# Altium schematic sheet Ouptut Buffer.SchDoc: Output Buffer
size 431 x 279 mm; Date: Not shown in title block; ApprovedBy: Not shown in title block; CheckedBy: Not shown in title block; Author: Not shown in title block; CompanyName: Not shown in title block; Engineer: Not shown in title block; Organization: Not shown in title block; Address1: Not shown in title block; Address2: Not shown in title block; Address3: Not shown in title block; Address4: Not shown in title block; DocumentNumber: 1; Revision: Use project parameter SCH_Rev; SheetNumber: 13; SheetTotal: 15; PageSetup: Record=PageOptions¦CenterHorizontal=True¦CenterVertical=True¦PrintScale=1.00¦XCorrection=1.00¦YCorrection=1.00¦PrintKind=0¦BorderSize=5000000¦LeftOffset=0¦BottomOffset=0¦Orientation=2¦PaperLength=1000¦PaperWidth=1000¦Scale=100¦PaperSource=15¦PrintQuality=600¦MediaType=1¦DitherType=10¦PaperKind=Letter¦PrintScaleMode=1
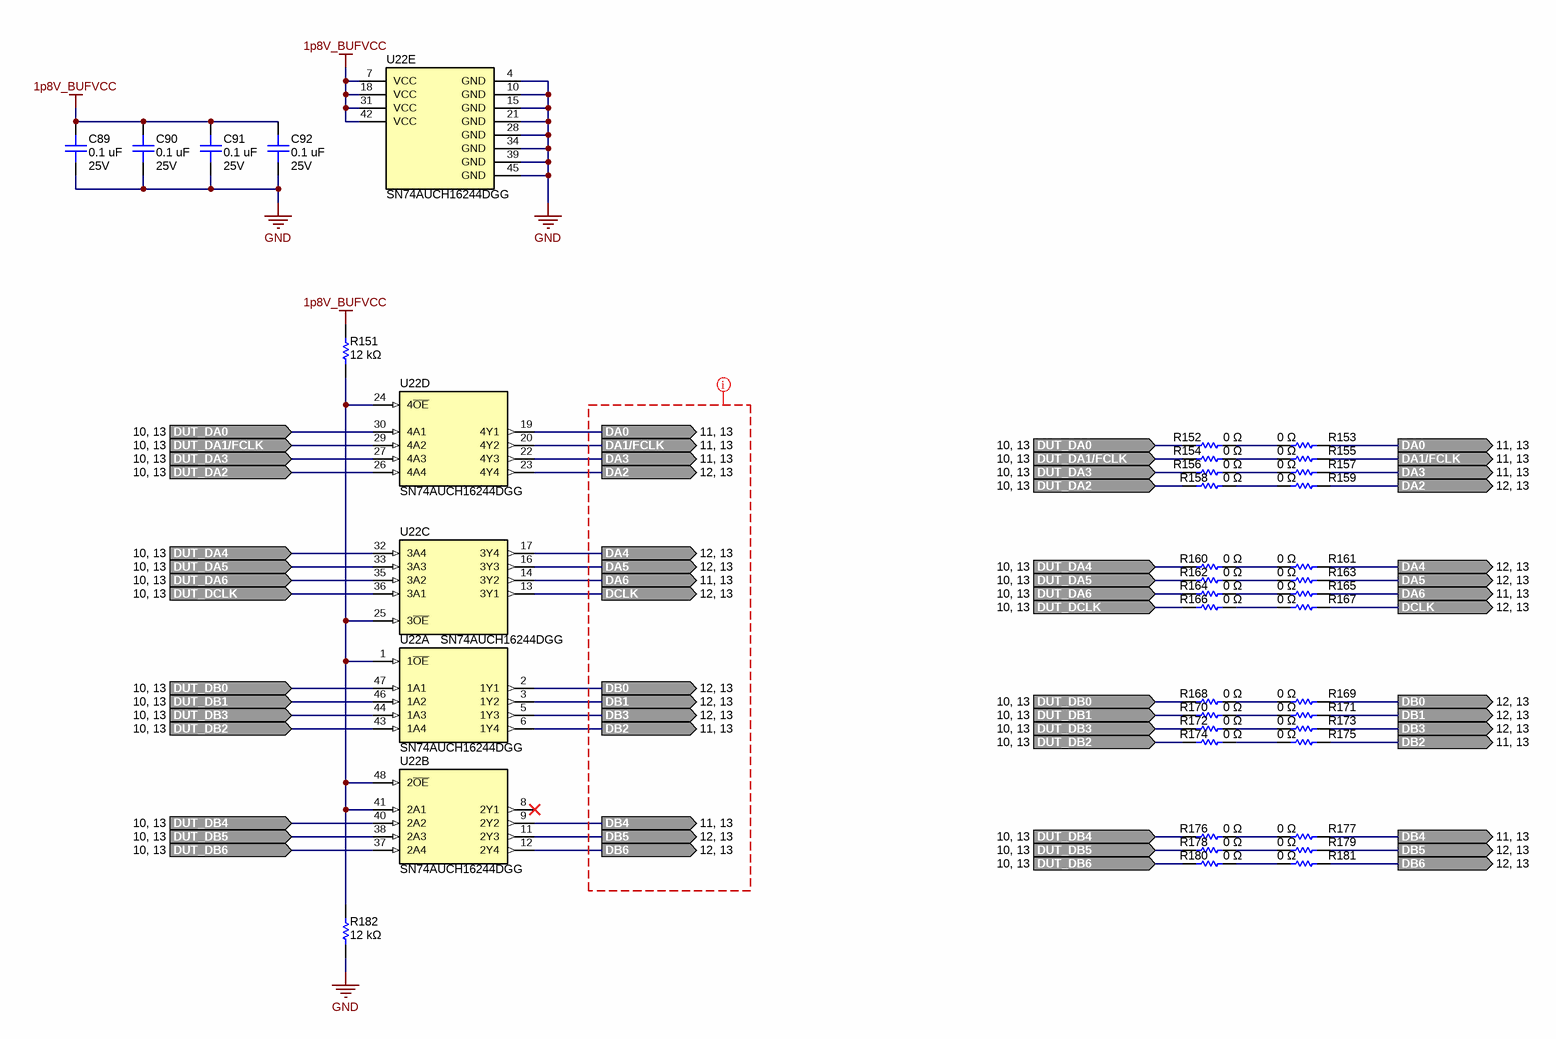
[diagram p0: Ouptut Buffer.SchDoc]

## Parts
C89  value 0.1 uF  Voltage - Rated: 25V  [0402L_cap]  (hidden comment: GRT155R71E104KE01J)
C90  value 0.1 uF  Voltage - Rated: 25V  [0402L_cap]  (hidden comment: GRT155R71E104KE01J)
C91  value 0.1 uF  Voltage - Rated: 25V  [0402L_cap]  (hidden comment: GRT155R71E104KE01J)
C92  value 0.1 uF  Voltage - Rated: 25V  [0402L_cap]  (hidden comment: GRT155R71E104KE01J)
R151  value 12 kΩ  [0201]  (hidden comment: ERJ-1GNJ123C)
R152  value 0 Ω  [0201]  (hidden comment: ERJ-1GN0R00C)
R153  value 0 Ω  [0201]  (hidden comment: ERJ-1GN0R00C)
R154  value 0 Ω  [0201]  (hidden comment: ERJ-1GN0R00C)
R155  value 0 Ω  [0201]  (hidden comment: ERJ-1GN0R00C)
R156  value 0 Ω  [0201]  (hidden comment: ERJ-1GN0R00C)
R157  value 0 Ω  [0201]  (hidden comment: ERJ-1GN0R00C)
R158  value 0 Ω  [0201]  (hidden comment: ERJ-1GN0R00C)
R159  value 0 Ω  [0201]  (hidden comment: ERJ-1GN0R00C)
R160  value 0 Ω  [0201]  (hidden comment: ERJ-1GN0R00C)
R161  value 0 Ω  [0201]  (hidden comment: ERJ-1GN0R00C)
R162  value 0 Ω  [0201]  (hidden comment: ERJ-1GN0R00C)
R163  value 0 Ω  [0201]  (hidden comment: ERJ-1GN0R00C)
R164  value 0 Ω  [0201]  (hidden comment: ERJ-1GN0R00C)
R165  value 0 Ω  [0201]  (hidden comment: ERJ-1GN0R00C)
R166  value 0 Ω  [0201]  (hidden comment: ERJ-1GN0R00C)
R167  value 0 Ω  [0201]  (hidden comment: ERJ-1GN0R00C)
R168  value 0 Ω  [0201]  (hidden comment: ERJ-1GN0R00C)
R169  value 0 Ω  [0201]  (hidden comment: ERJ-1GN0R00C)
R170  value 0 Ω  [0201]  (hidden comment: ERJ-1GN0R00C)
R171  value 0 Ω  [0201]  (hidden comment: ERJ-1GN0R00C)
R172  value 0 Ω  [0201]  (hidden comment: ERJ-1GN0R00C)
R173  value 0 Ω  [0201]  (hidden comment: ERJ-1GN0R00C)
R174  value 0 Ω  [0201]  (hidden comment: ERJ-1GN0R00C)
R175  value 0 Ω  [0201]  (hidden comment: ERJ-1GN0R00C)
R176  value 0 Ω  [0201]  (hidden comment: ERJ-1GN0R00C)
R177  value 0 Ω  [0201]  (hidden comment: ERJ-1GN0R00C)
R178  value 0 Ω  [0201]  (hidden comment: ERJ-1GN0R00C)
R179  value 0 Ω  [0201]  (hidden comment: ERJ-1GN0R00C)
R180  value 0 Ω  [0201]  (hidden comment: ERJ-1GN0R00C)
R181  value 0 Ω  [0201]  (hidden comment: ERJ-1GN0R00C)
R182  value 12 kΩ  [0201]  (hidden comment: ERJ-1GNJ123C)
U22  SN74AUCH16244DGG  [DGG0048A]  (parts A,B,C,D,E of 5)

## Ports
DA0 (out, see 11, 13), DA1/FCLK (out, see 11, 13), DA2 (out, see 12, 13), DA3 (out, see 11, 13), DA4 (out, see 12, 13), DA5 (out, see 12, 13), DA6 (out, see 11, 13), DB0 (out, see 12, 13), DB1 (out, see 12, 13), DB2 (out, see 11, 13), DB3 (out, see 12, 13), DB4 (out, see 11, 13), DB5 (out, see 12, 13), DB6 (out, see 12, 13), DCLK (out, see 12, 13), DUT_DA0 (in, see 10, 13), DUT_DA1/FCLK (in, see 10, 13), DUT_DA2 (in, see 10, 13), DUT_DA3 (in, see 10, 13), DUT_DA4 (in, see 10, 13), DUT_DA5 (in, see 10, 13), DUT_DA6 (in, see 10, 13), DUT_DB0 (in, see 10, 13), DUT_DB1 (in, see 10, 13), DUT_DB2 (in, see 10, 13), DUT_DB3 (in, see 10, 13), DUT_DB4 (in, see 10, 13), DUT_DB5 (in, see 10, 13), DUT_DB6 (in, see 10, 13), DUT_DCLK (in, see 10, 13)

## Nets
1p8V_BUFVCC: C89.2 C90.2 C91.2 C92.2 R151.2 U22.7(VCC) U22.18(VCC) U22.31(VCC) U22.42(VCC)
GND: C89.1 C90.1 C91.1 C92.1 R182.1 U22.4(GND) U22.10(GND) U22.15(GND) U22.21(GND) U22.28(GND) U22.34(GND) U22.39(GND) U22.45(GND)
DA0: R153.2 U22.19(4Y1) ; port DA0
DA1/FCLK: R155.2 U22.20(4Y2) ; port DA1/FCLK
DA2: R159.2 U22.23(4Y4) ; port DA2
DA3: R157.2 U22.22(4Y3) ; port DA3
DA4: R161.2 U22.17(3Y4) ; port DA4
DA5: R163.2 U22.16(3Y3) ; port DA5
DA6: R165.2 U22.14(3Y2) ; port DA6
DB0: R169.2 U22.2(1Y1) ; port DB0
DB1: R171.2 U22.3(1Y2) ; port DB1
DB2: R175.2 U22.6(1Y4) ; port DB2
DB3: R173.2 U22.5(1Y3) ; port DB3
DB4: R177.2 U22.9(2Y2) ; port DB4
DB5: R179.2 U22.11(2Y3) ; port DB5
DB6: R181.2 U22.12(2Y4) ; port DB6
DCLK: R167.2 U22.13(3Y1) ; port DCLK
DUT_DA0: R152.1 U22.30(4A1) ; port DUT_DA0
DUT_DA1/FCLK: R154.1 U22.29(4A2) ; port DUT_DA1/FCLK
DUT_DA2: R158.1 U22.26(4A4) ; port DUT_DA2
DUT_DA3: R156.1 U22.27(4A3) ; port DUT_DA3
DUT_DA4: R160.1 U22.32(3A4) ; port DUT_DA4
DUT_DA5: R162.1 U22.33(3A3) ; port DUT_DA5
DUT_DA6: R164.1 U22.35(3A2) ; port DUT_DA6
DUT_DB0: R168.1 U22.47(1A1) ; port DUT_DB0
DUT_DB1: R170.1 U22.46(1A2) ; port DUT_DB1
DUT_DB2: R174.1 U22.43(1A4) ; port DUT_DB2
DUT_DB3: R172.1 U22.44(1A3) ; port DUT_DB3
DUT_DB4: R176.1 U22.40(2A2) ; port DUT_DB4
DUT_DB5: R178.1 U22.38(2A3) ; port DUT_DB5
DUT_DB6: R180.1 U22.37(2A4) ; port DUT_DB6
DUT_DCLK: R166.1 U22.36(3A1) ; port DUT_DCLK
NetR151_1: R151.1 R182.2 U22.1(1~{OE}) U22.24(4~{OE}) U22.25(3~{OE}) U22.41(2A1) U22.48(2~{OE})
NetR152_2: R152.2 R153.1
NetR154_2: R154.2 R155.1
NetR156_2: R156.2 R157.1
NetR158_2: R158.2 R159.1
NetR160_2: R160.2 R161.1
NetR162_2: R162.2 R163.1
NetR164_2: R164.2 R165.1
NetR166_2: R166.2 R167.1
NetR168_2: R168.2 R169.1
NetR170_2: R170.2 R171.1
NetR172_2: R172.2 R173.1
NetR174_2: R174.2 R175.1
NetR176_2: R176.2 R177.1
NetR178_2: R178.2 R179.1
NetR180_2: R180.2 R181.1

Not connected (* = marked no-connect by the designer): U22 8(2Y1)*

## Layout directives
net class CMOS_BUF_Out: (no net found under the mark)

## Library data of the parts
C89-C92 = capcc09401: CAP CER 0.1UF 25V X7R 0402; Manufacturer: Murata; CompType: Capacitor Ceramic; Tolerance: ±10%; SizeX_mm: 1; SizeY_mm: 0.5; SizeZ_mm: 0.7
R151 R182 = RSMD020101206: RES SMD 12K OHM 5% 1/20W 0201; Manufacturer: Panasonic Electronic Components; CompType: Resistor SMD; Power (Watts): 0.05W, 1/20W; Temperature Coefficient: ±200ppm/°C
R152-R181 = RSMD020101699: RES SMD 0 OHM JUMPER 1/20W 0201; Manufacturer: Panasonic Electronic Components; CompType: Resistor SMD; Power (Watts): 0.05W, 1/20W
U22 = SN74AUCH16244DGG: 16-ch, 0.8-V to 2.7-V high speed buffers with bus-hold and 3-state outputs; Manufacturer: Texas Instruments; CompType: Buffer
